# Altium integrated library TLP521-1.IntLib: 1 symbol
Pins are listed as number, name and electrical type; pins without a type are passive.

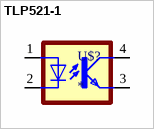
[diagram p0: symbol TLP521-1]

## TLP521-1
designator U$?
Optoisolator Transistor Output 5300Vrms 1 Channel 4-DIP; MF: Isocom; MP: TLP521-1
footprint DIL04
pins: 1 A, 2 C, 3 EMIT, 4 COL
